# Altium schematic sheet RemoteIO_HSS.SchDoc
size 431 x 279 mm; Date: Not shown in title block; ApprovedBy: Not shown in title block; CheckedBy: Not shown in title block; Author: Not shown in title block; CompanyName: Not shown in title block; Engineer: Not shown in title block; Organization: Not shown in title block; Address1: Not shown in title block; Address2: Not shown in title block; Address3: Not shown in title block; Address4: Not shown in title block; DocumentNumber: 4; Revision: Use project parameter SCH_Rev; SheetNumber: 4; SheetTotal: 14; PageSetup: Record=PageOptions¦CenterHorizontal=True¦CenterVertical=True¦PrintScale=1.00¦XCorrection=1.00¦YCorrection=1.00¦PrintKind=0¦BorderSize=5000000¦LeftOffset=0¦BottomOffset=0¦Orientation=2¦PaperLength=1000¦PaperWidth=1000¦Scale=100¦PaperSource=15¦PrintQuality=600¦MediaType=1¦DitherType=10¦PaperKind=Letter¦PrintScaleMode=1
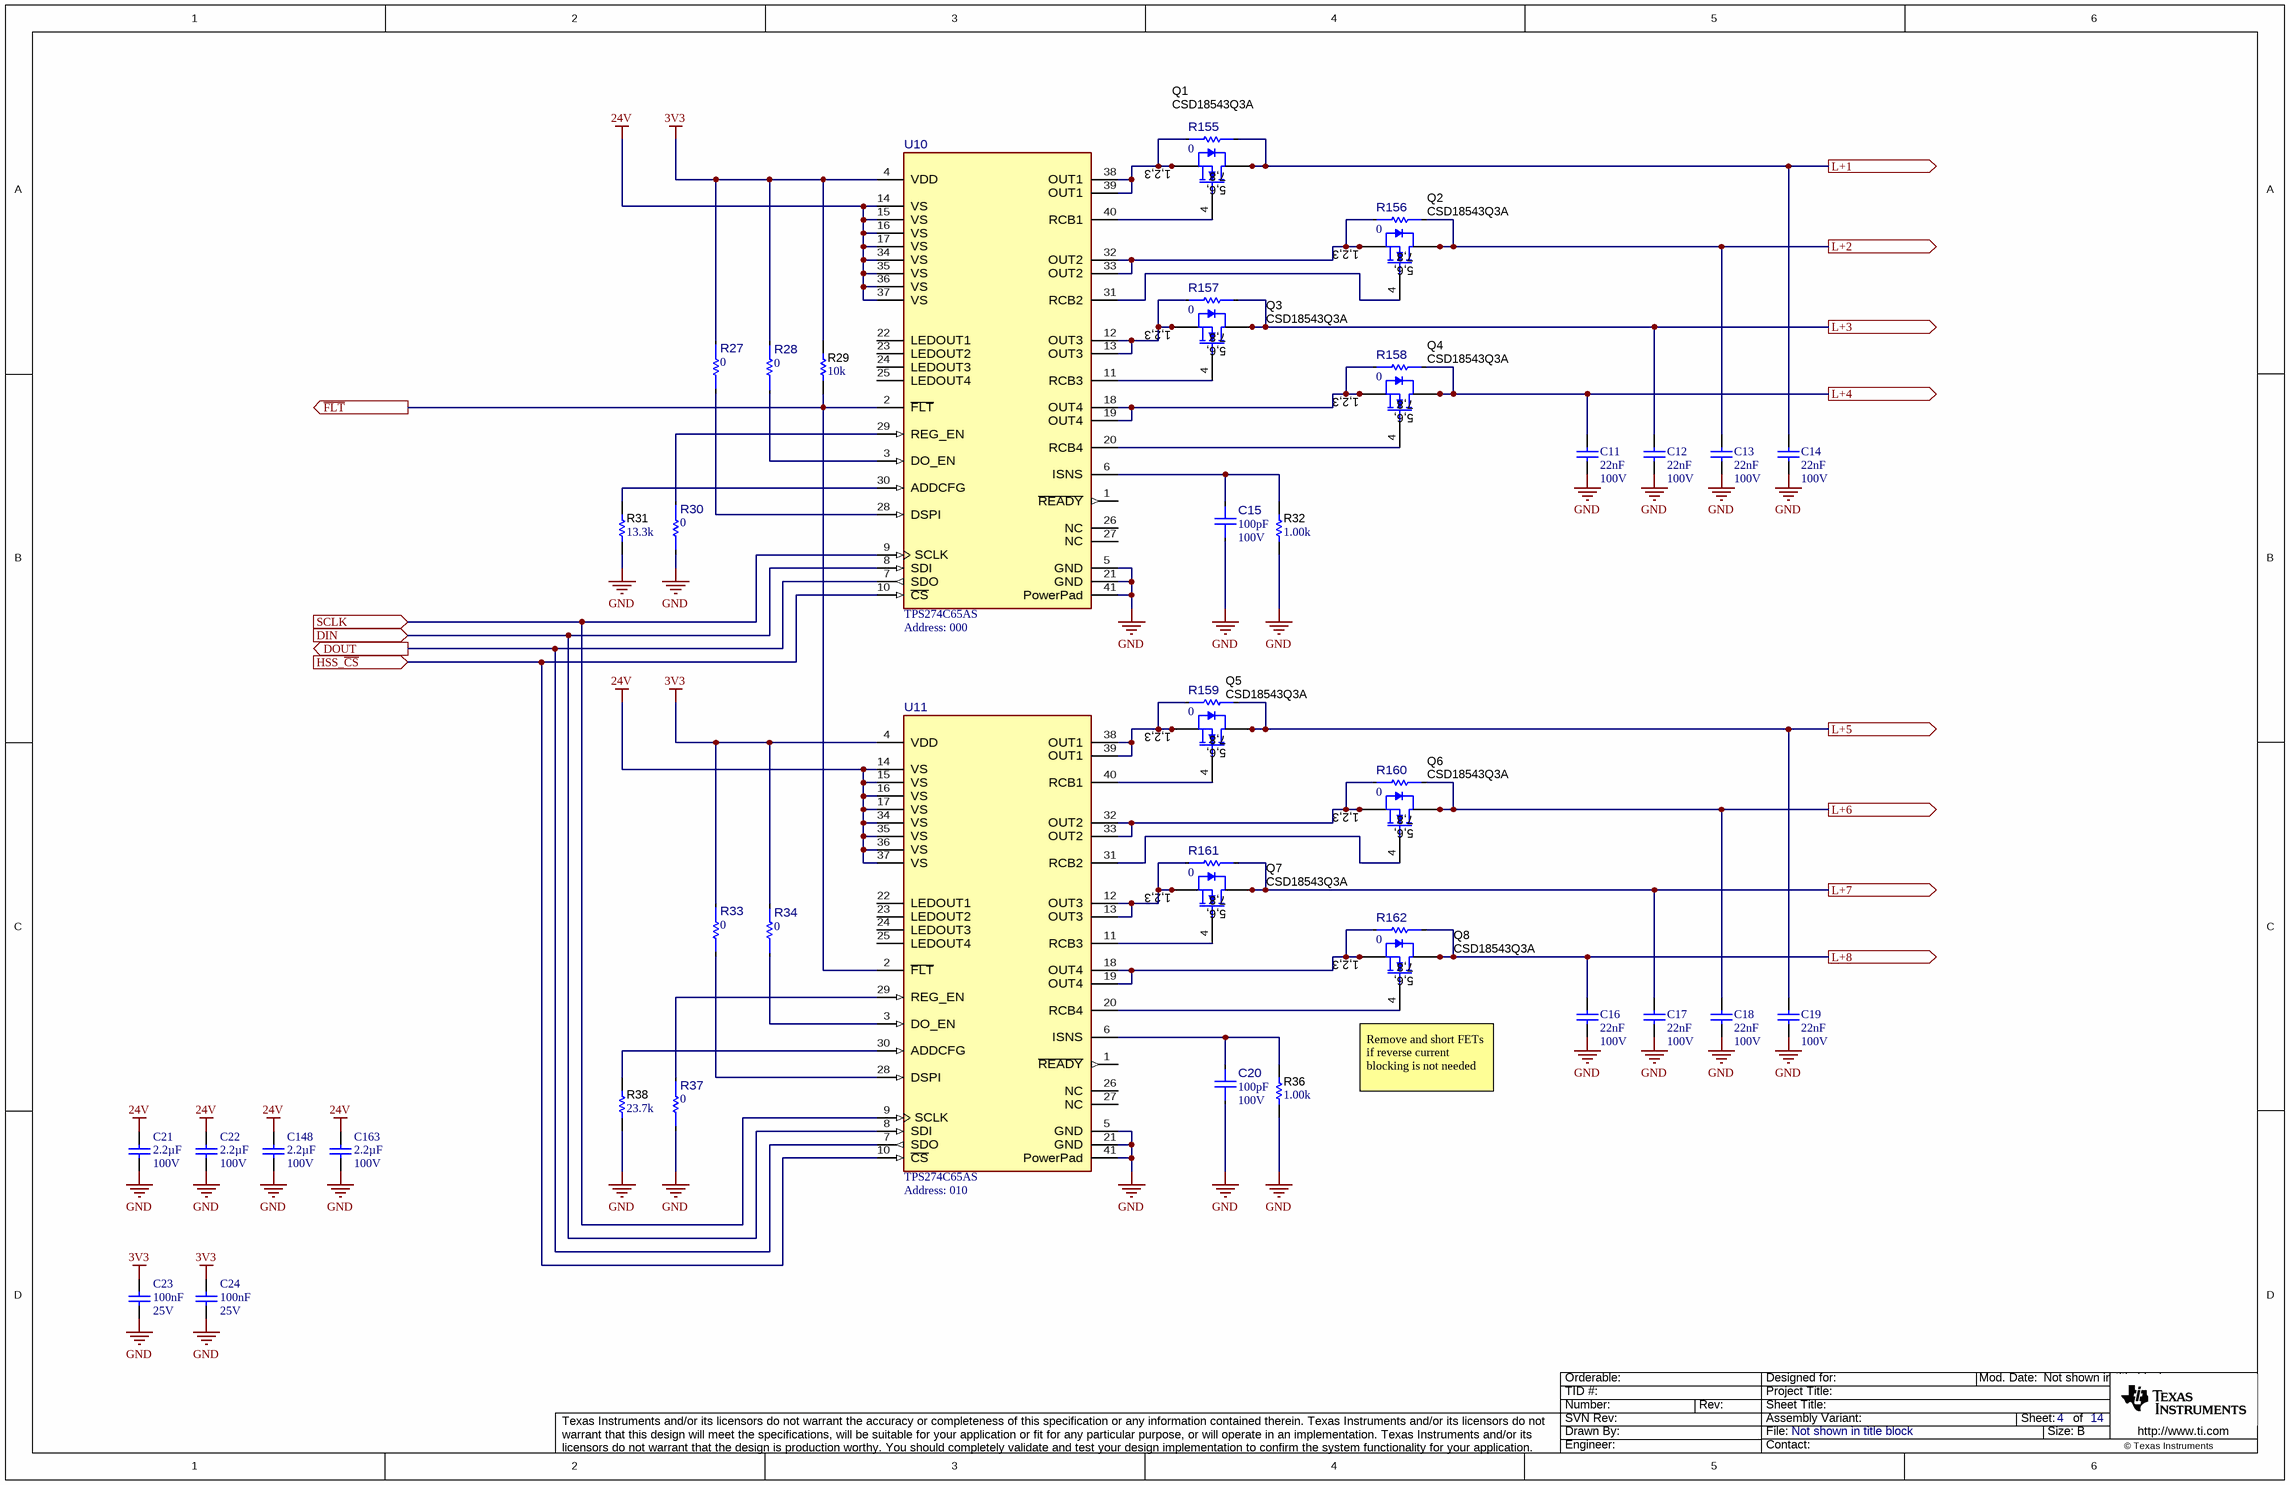
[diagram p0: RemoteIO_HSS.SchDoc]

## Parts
C11  Cap_F: 22nF  Rated Voltage (DC): 100V  [WCAP-CSGP_0805_L2W1.25H0.8_Reflow]  (hidden comment: 885012207124)
C12  Cap_F: 22nF  Rated Voltage (DC): 100V  [WCAP-CSGP_0805_L2W1.25H0.8_Reflow]  (hidden comment: 885012207124)
C13  Cap_F: 22nF  Rated Voltage (DC): 100V  [WCAP-CSGP_0805_L2W1.25H0.8_Reflow]  (hidden comment: 885012207124)
C14  Cap_F: 22nF  Rated Voltage (DC): 100V  [WCAP-CSGP_0805_L2W1.25H0.8_Reflow]  (hidden comment: 885012207124)
C15  ValueDisplayed: 100pF  VDC_V: 100V  [FP-885012005080_0402-MFG]  (hidden comment: 885012005080)
C16  Cap_F: 22nF  Rated Voltage (DC): 100V  [WCAP-CSGP_0805_L2W1.25H0.8_Reflow]  (hidden comment: 885012207124)
C17  Cap_F: 22nF  Rated Voltage (DC): 100V  [WCAP-CSGP_0805_L2W1.25H0.8_Reflow]  (hidden comment: 885012207124)
C18  Cap_F: 22nF  Rated Voltage (DC): 100V  [WCAP-CSGP_0805_L2W1.25H0.8_Reflow]  (hidden comment: 885012207124)
C19  Cap_F: 22nF  Rated Voltage (DC): 100V  [WCAP-CSGP_0805_L2W1.25H0.8_Reflow]  (hidden comment: 885012207124)
C20  ValueDisplayed: 100pF  VDC_V: 100V  [FP-885012005080_0402-MFG]  (hidden comment: 885012005080)
C21  Cap_F: 2.2µF  Rated Voltage (DC): 100V  [WCAP-CSGP_1210_L3.2W2.5H2.5]  (hidden comment: 885012209071)
C22  Cap_F: 2.2µF  Rated Voltage (DC): 100V  [WCAP-CSGP_1210_L3.2W2.5H2.5]  (hidden comment: 885012209071)
C23  Cap_F: 100nF  Rated Voltage (DC): 25V  [WCAP-CSGP_0402_L1W0.5H0.5]  (hidden comment: 885012105018)
C24  Cap_F: 100nF  Rated Voltage (DC): 25V  [WCAP-CSGP_0402_L1W0.5H0.5]  (hidden comment: 885012105018)
C148  Cap_F: 2.2µF  Rated Voltage (DC): 100V  [WCAP-CSGP_1210_L3.2W2.5H2.5]  (hidden comment: 885012209071)
C163  Cap_F: 2.2µF  Rated Voltage (DC): 100V  [WCAP-CSGP_1210_L3.2W2.5H2.5]  (hidden comment: 885012209071)
Q1  CSD18543Q3A  [DNH0008A]
Q2  CSD18543Q3A  [DNH0008A]
Q3  CSD18543Q3A  [DNH0008A]
Q4  CSD18543Q3A  [DNH0008A]
Q5  CSD18543Q3A  [DNH0008A]
Q6  CSD18543Q3A  [DNH0008A]
Q7  CSD18543Q3A  [DNH0008A]
Q8  CSD18543Q3A  [DNH0008A]
R27  value 0  [FP-CRCW04020000Z0EDC_0402-MFG]  (hidden comment: CRCW04020000Z0EDC)
R28  value 0  [FP-CRCW04020000Z0EDC_0402-MFG]  (hidden comment: CRCW04020000Z0EDC)
R29  ValueDisplayed: 10k  [0402]  (hidden comment: CRCW040210K0JNED)
R30  value 0  [FP-CRCW04020000Z0EDC_0402-MFG]  (hidden comment: CRCW04020000Z0EDC)
R31  ValueDisplayed: 13.3k  [0402]  (hidden comment: CRCW040213K3FKED)
R32  ValueDisplayed: 1.00k  [0402]  (hidden comment: CRCW04021K00FKED)
R33  value 0  [FP-CRCW04020000Z0EDC_0402-MFG]  (hidden comment: CRCW04020000Z0EDC)
R34  value 0  [FP-CRCW04020000Z0EDC_0402-MFG]  (hidden comment: CRCW04020000Z0EDC)
R36  ValueDisplayed: 1.00k  [0402]  (hidden comment: CRCW04021K00FKED)
R37  value 0  [FP-CRCW04020000Z0EDC_0402-MFG]  (hidden comment: CRCW04020000Z0EDC)
R38  ValueDisplayed: 23.7k  [0402]  (hidden comment: CRCW040223K7FKED)
R155  value 0  [FP-CRCW04020000Z0EDC_0402-MFG]  (hidden comment: CRCW04020000Z0EDC)
R156  value 0  [FP-CRCW04020000Z0EDC_0402-MFG]  (hidden comment: CRCW04020000Z0EDC)
R157  value 0  [FP-CRCW04020000Z0EDC_0402-MFG]  (hidden comment: CRCW04020000Z0EDC)
R158  value 0  [FP-CRCW04020000Z0EDC_0402-MFG]  (hidden comment: CRCW04020000Z0EDC)
R159  value 0  [FP-CRCW04020000Z0EDC_0402-MFG]  (hidden comment: CRCW04020000Z0EDC)
R160  value 0  [FP-CRCW04020000Z0EDC_0402-MFG]  (hidden comment: CRCW04020000Z0EDC)
R161  value 0  [FP-CRCW04020000Z0EDC_0402-MFG]  (hidden comment: CRCW04020000Z0EDC)
R162  value 0  [FP-CRCW04020000Z0EDC_0402-MFG]  (hidden comment: CRCW04020000Z0EDC)
U10  TPS274C65AS  [RHA0040M-MFG]
U11  TPS274C65AS  [RHA0040M-MFG]

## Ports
DIN (in), DOUT (out), HSS_~{CS} (in), L+1 (out), L+2 (out), L+3 (out), L+4 (out), L+5 (out), L+6 (out), L+7 (out), L+8 (out), SCLK (in), ~{FLT} (out)

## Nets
3V3: C23.2 C24.2 R27.1 R28.2 R29.2 R33.1 R34.2 U10.4(VDD) U11.4(VDD)
24V: C21.2 C22.2 C148.2 C163.2 U10.14(VS) U10.15(VS) U10.16(VS) U10.17(VS) U10.34(VS) U10.35(VS) U10.36(VS) U10.37(VS) U11.14(VS) U11.15(VS) U11.16(VS) U11.17(VS) U11.34(VS) U11.35(VS) U11.36(VS) U11.37(VS)
GND: C11.1 C12.1 C13.1 C14.1 C15.1 C16.1 C17.1 C18.1 C19.1 C20.1 C21.1 C22.1 C23.1 C24.1 C148.1 C163.1 R30.2 R31.1 R32.1 R36.1 R37.2 R38.1 U10.5(GND) U10.21(GND) U10.41(PowerPad) U11.5(GND) U11.21(GND) U11.41(PowerPad)
~{FLT}: R29.1 U10.2(~{FLT}) U11.2(~{FLT}) ; port ~{FLT}
DIN: U10.8(SDI) U11.8(SDI) ; port DIN
DOUT: U10.7(SDO) U11.7(SDO) ; port DOUT
HSS_~{CS}: U10.10(~{CS}) U11.10(~{CS}) ; port HSS_~{CS}
L+1: C14.2 Q1.5(D) Q1.6(D) Q1.7(D) Q1.8(D) Q1.9(D) R155.2 ; port L+1
L+2: C13.2 Q2.5(D) Q2.6(D) Q2.7(D) Q2.8(D) Q2.9(D) R156.2 ; port L+2
L+3: C12.2 Q3.5(D) Q3.6(D) Q3.7(D) Q3.8(D) Q3.9(D) R157.2 ; port L+3
L+4: C11.2 Q4.5(D) Q4.6(D) Q4.7(D) Q4.8(D) Q4.9(D) R158.2 ; port L+4
L+5: C19.2 Q5.5(D) Q5.6(D) Q5.7(D) Q5.8(D) Q5.9(D) R159.2 ; port L+5
L+6: C18.2 Q6.5(D) Q6.6(D) Q6.7(D) Q6.8(D) Q6.9(D) R160.2 ; port L+6
L+7: C17.2 Q7.5(D) Q7.6(D) Q7.7(D) Q7.8(D) Q7.9(D) R161.2 ; port L+7
L+8: C16.2 Q8.5(D) Q8.6(D) Q8.7(D) Q8.8(D) Q8.9(D) R162.2 ; port L+8
SCLK: U10.9(SCLK) U11.9(SCLK) ; port SCLK
NetC15_2: C15.2 R32.2 U10.6(ISNS)
NetC20_2: C20.2 R36.2 U11.6(ISNS)
NetQ1_1: Q1.1(S) Q1.2(S) Q1.3(S) R155.1 U10.38(OUT1) U10.39(OUT1)
NetQ1_4: Q1.4(G) U10.40(RCB1)
NetQ2_1: Q2.1(S) Q2.2(S) Q2.3(S) R156.1 U10.32(OUT2) U10.33(OUT2)
NetQ2_4: Q2.4(G) U10.31(RCB2)
NetQ3_1: Q3.1(S) Q3.2(S) Q3.3(S) R157.1 U10.12(OUT3) U10.13(OUT3)
NetQ3_4: Q3.4(G) U10.11(RCB3)
NetQ4_1: Q4.1(S) Q4.2(S) Q4.3(S) R158.1 U10.18(OUT4) U10.19(OUT4)
NetQ4_4: Q4.4(G) U10.20(RCB4)
NetQ5_1: Q5.1(S) Q5.2(S) Q5.3(S) R159.1 U11.38(OUT1) U11.39(OUT1)
NetQ5_4: Q5.4(G) U11.40(RCB1)
NetQ6_1: Q6.1(S) Q6.2(S) Q6.3(S) R160.1 U11.32(OUT2) U11.33(OUT2)
NetQ6_4: Q6.4(G) U11.31(RCB2)
NetQ7_1: Q7.1(S) Q7.2(S) Q7.3(S) R161.1 U11.12(OUT3) U11.13(OUT3)
NetQ7_4: Q7.4(G) U11.11(RCB3)
NetQ8_1: Q8.1(S) Q8.2(S) Q8.3(S) R162.1 U11.18(OUT4) U11.19(OUT4)
NetQ8_4: Q8.4(G) U11.20(RCB4)
NetR27_2: R27.2 U10.28(DSPI)
NetR28_1: R28.1 U10.3(DO_EN)
NetR30_1: R30.1 U10.29(REG_EN)
NetR31_2: R31.2 U10.30(ADDCFG)
NetR33_2: R33.2 U11.28(DSPI)
NetR34_1: R34.1 U11.3(DO_EN)
NetR37_1: R37.1 U11.29(REG_EN)
NetR38_2: R38.2 U11.30(ADDCFG)

Not connected (* = marked no-connect by the designer): U10 1(~{READY}) 22(LEDOUT1) 23(LEDOUT2) 24(LEDOUT3) 25(LEDOUT4) 26(NC) 27(NC); U11 1(~{READY}) 22(LEDOUT1) 23(LEDOUT2) 24(LEDOUT3) 25(LEDOUT4) 26(NC) 27(NC)

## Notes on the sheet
- (near U10) Address: 000
- (near Q8) Remove and short FETs if reverse current blocking is not needed
- (near U11) Address: 010

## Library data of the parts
C11-C14 C16-C19 = CMP-0119538-1: WCAP-CSGP Multilayer Ceramic Chip Capacitor, General Purpose, size 0805, X7R, 22nF, 100VDC; Manufacturer: Wurth Elektronik; Capacitance Tolerance: +/-10%; Case/Size Code: 0805; Dissipation Factor: 2.5%; Insulation Resistance: 4.5GOhm; Technical Reference: X7R0805223K100DFCT10000
C15 C20 = CMP-0097308-1: 100 pF ±5% 100V Ceramic Capacitor C0G, NP0 0402 (1005 Metric); Manufacturer: Wurth Electronics; Value: 100pF; SizeZ_mm: 0.55mm; TempCo: 30ppm/°C; AEC Qualified: No
C21 C22 C148 C163 = CMP-0119705-1: WCAP-CSGP Multilayer Ceramic Chip Capacitor, General Purpose, size 1210, X7R, 2.2µF, 100VDC; Manufacturer: Wurth Elektronik; PartNumber: '885012209071; Capacitance Tolerance: +/-10%; Case/Size Code: 1210; Dissipation Factor: 5%; Insulation Resistance: 0.05GOhm; Technical Reference: X7R1210225K100DFCT10000
C23 C24 = CMP-0119143-1: WCAP-CSGP Multilayer Ceramic Chip Capacitor, General Purpose, size 0402, X5R, 100nF, 25VDC; Manufacturer: Wurth Elektronik; PartNumber: '885012105018; Capacitance Tolerance: +/-20%; Case/Size Code: 0402; Dissipation Factor: 10%; Insulation Resistance: 5GOhm; Technical Reference: X5R0402104M025DFCT10000
Q1-Q8 = CMP-0000826-2: MOSFET, N-CH, 60 V, 35 A, DNH0008A (VSONP-8); Alternate Manufacturer: None; Manufacturer: Texas Instruments; SizeZ_mm: 0.9; ChType: N; Value2: 11.1 nC; Value1: 0.01; VdsMax_V: 60V; SizeX_mm: 3.3; SizeAreaWB_mm2: 18.49; Vgs_V: 20V; QgTyp_nC: 11.1; Value: 60V; Rdson45_ohm: 12m; SizeArea_mm2: 10.89; AEC Category: Q101; IdsMax_A: 35A; ChMode: Enhancement
R27 R28 R30 R33 R34 R37 R155-R162 = CMP-0093210-1: Jumper 0.063W, 1/16W Chip Resistor 0402 (1005 Metric) - Thick Film; Manufacturer: Vishay; AEC Qualified: No; VDC_V: 50V; Power_W: 63mW; SizeZ_mm: 0.35mm
R29 = CMP-0026825-5: RES, 10 k, 5%, 0.063 W, AEC-Q200 Grade 0, 0402; Manufacturer: Vishay-Dale; Power_W: 63mW; TempCo: 200 ppm/C; Value_Code: 10k0; Value: 10k; EIA_Code: E24; SizeX_mm: 1; SizeY_mm: 0.5; SizeZ_mm: 0.6; Value2: 0.063W; AEC Qualified: Y; VDC_V: 50V; AEC Category: Q200; AEC Grade: 0
R31 = CMP-0026004-3: RES, 13.3 k, 1%, 0.063 W, AEC-Q200 Grade 0, 0402; Manufacturer: Vishay-Dale; Power_W: 63mW; TempCo: 100 ppm/C; Value_Code: 13k3; Value: 13.3k; EIA_Code: E96; SizeX_mm: 1; SizeY_mm: 0.5; SizeZ_mm: 0.6; Value2: 0.063W; AEC Qualified: Y; VDC_V: 50V; AEC Category: Q200; AEC Grade: 0
R32 R36 = CMP-0026071-3: RES, 1.00 k, 1%, 0.063 W, AEC-Q200 Grade 0, 0402; Manufacturer: Vishay-Dale; Power_W: 63mW; TempCo: 100 ppm/C; Value_Code: 1k00; Value: 1.00k; EIA_Code: E96; Res_ohm: 1k; SizeX_mm: 1; SizeY_mm: 0.5; SizeZ_mm: 0.6; Value2: 0.063W; AEC Qualified: Y; VDC_V: 50V; AEC Category: Q200; AEC Grade: 0
R38 = CMP-0026187-2: RES, 23.7 k, 1%, 0.063 W, AEC-Q200 Grade 0, 0402; Manufacturer: Vishay-Dale; Power_W: 63mW; TempCo: 100 ppm/C; Value_Code: 23k7; Value: 23.7k; EIA_Code: E96; SizeX_mm: 1; SizeY_mm: 0.5; SizeZ_mm: 0.6; Value2: 0.063W; AEC Qualified: Y; VDC_V: 50V; AEC Category: Q200; AEC Grade: 0
U10 U11 = CMP-0093389-2: 65-mΩ, Quad-Channel Smart High-Side Switch with SPI interface and Diagnostics; Manufacturer: Texas Instruments; AEC Category: Q200; Max Supply Voltage: 36V; Turn On Delay Time: 30us; CompType: IC; AEC Qualified: No; Min Supply Voltage: 3V; Number Of Drivers: 4; TaMin_C: -40°C; TJmax_C: +150°C; Standoff Height: 0mm; TaMax_C: +125°C; SizeZ_mm: 1mm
